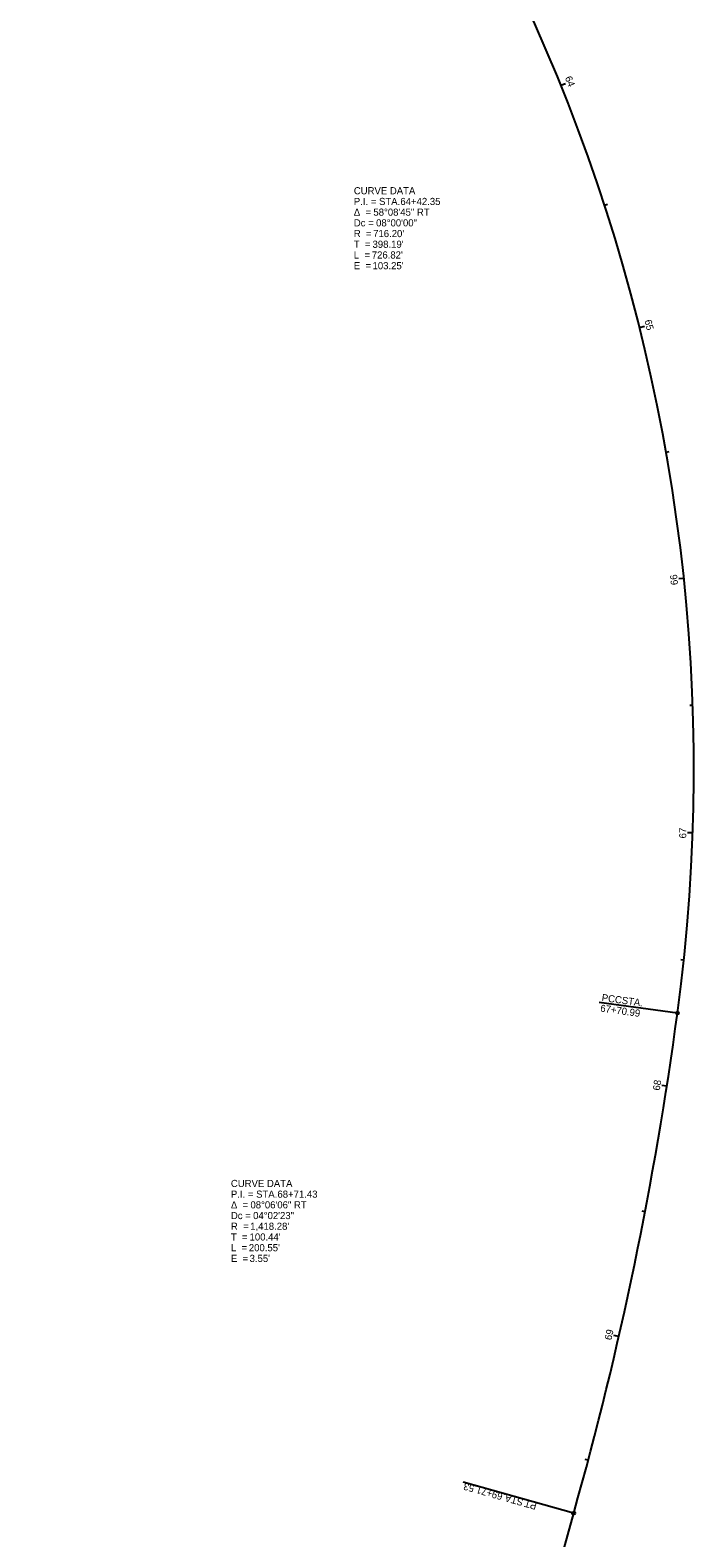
# Model space of a CAD drawing. Extents: x 2200534 to 2201952, y 633824 to 635634.
# Drawn here: x 2201692 to 2201952, y 634138 to 634730 of the extents above; entities that cross this region are included whole.
import ezdxf

# ---------------------------------------------------------------- set-up
doc = ezdxf.new("R2010")
doc.units = 0
for name, color, linetype in [('_CIVIL_CONSTRUCTION', 7, 'Continuous'), ('RW_X_CL', 7, 'Continuous'), ('RW_X_CL_100_Cardinal_Points', 7, 'Continuous'), ('SH_Data', 7, 'Continuous')]:
    doc.layers.add(name, color=color, linetype=linetype)

msp = doc.modelspace()

# ---------------------------------------------------------------- linework, layer by layer
at = {"layer": 'RW_X_CL'}
for p, q in [((2201946.02, 634344.04), (2201915.27, 634348.19)), ((2201905.29, 634147.85), (2201861.98, 634160.08))]:
    msp.add_line(p, q, dxfattribs=at)
for centre in [(2201946.02, 634344.04), (2201905.29, 634147.85)]:
    msp.add_circle(centre, 0.6, dxfattribs=at)
at = {"layer": 'RW_X_CL_100_Cardinal_Points'}
for p, q in [((2201900.27, 634708.03), (2201902.12, 634708.78)), ((2201917.37, 634661.06), (2201918.51, 634661.43)), ((2201931.15, 634613.01), (2201933.09, 634613.49)), ((2201941.55, 634564.11), (2201942.73, 634564.32)), ((2201948.51, 634514.61), (2201946.52, 634514.4)), ((2201952, 634464.74), (2201950.8, 634464.7)), ((2201952, 634414.75), (2201950, 634414.82)), ((2201948.51, 634364.88), (2201947.32, 634365.01)), ((2201941.85, 634315.33), (2201939.87, 634315.64)), ((2201933.29, 634266.07), (2201932.11, 634266.3)), ((2201923, 634217.15), (2201921.05, 634217.59)), ((2201910.99, 634168.61), (2201909.83, 634168.92))]:
    msp.add_line(p, q, dxfattribs=at)
at = {"layer": 'SH_Data'}
msp.add_line((2201905.29, 634147.85), (2201818.25, 633839.81), dxfattribs=at)
for centre, radius, start, end in [((2201236.24, 634439.71), 716.2, 352.32377, 50.4696), ((2201236.24, 634439.71), 716.2, 352.32377, 50.4696), ((2201236.24, 634439.71), 716.2, 352.32377, 50.4696), ((2200540.45, 634533.49), 1418.28, 344.2221, 352.32377), ((2200540.45, 634533.49), 1418.28, 344.2221, 352.32377)]:
    msp.add_arc(centre, radius, start, end, dxfattribs=at)

# ---------------------------------------------------------------- texts
at = {"layer": '_CIVIL_CONSTRUCTION'}
for s, p in [('CURVE DATA', (2201819.05, 634665.27)), ('P.I. = STA. ', (2201819.05, 634661.07)), ('64+42.35', (2201837.32, 634661.07)), ('Δ  = ', (2201819.05, 634656.87)), ('58°08\'45" RT', (2201826.73, 634656.87)), ('Dc = ', (2201819.05, 634652.67)), ('08°00\'00"', (2201827.79, 634652.67)), ('T  = ', (2201819.05, 634644.27)), ('R  = ', (2201819.05, 634648.47)), ("398.19'", (2201826.39, 634644.27)), ("716.20'", (2201826.63, 634648.47)), ('L  = ', (2201819.05, 634640.07)), ("726.82'", (2201826.09, 634640.07)), ('E  = ', (2201819.05, 634635.87)), ("103.25'", (2201826.39, 634635.87)), ('CURVE DATA', (2201770.83, 634275.83)), ('P.I. = STA. ', (2201770.83, 634271.63)), ('68+71.43', (2201789.09, 634271.63)), ('Δ  = ', (2201770.83, 634267.43)), ('08°06\'06" RT', (2201778.5, 634267.43)), ('Dc = ', (2201770.83, 634263.23)), ('R  = ', (2201770.83, 634259.03)), ("1,418.28'", (2201778.41, 634259.03)), ('04°02\'23"', (2201779.56, 634263.23)), ('T  = ', (2201770.83, 634254.83)), ("100.44'", (2201778.16, 634254.83)), ('L  = ', (2201770.83, 634250.63)), ('E  = ', (2201770.83, 634246.43)), ("200.55'", (2201777.87, 634250.63)), ("3.55'", (2201778.17, 634246.43))]:
    msp.add_text(s, height=2.8, dxfattribs=at).set_placement(p)
at = {"layer": 'RW_X_CL'}
for s, rotation, p in [('PCC', 352.32377, (2201916.16, 634348.81)), (' STA. ', 352.32377, (2201922.99, 634347.89)), ('67+70.99', 352.32377, (2201915.6, 634344.65)), ('69+71.53', 164.2221, (2201877.7, 634155.6)), (' STA. ', 164.2221, (2201886.8, 634153.03)), ('PT', 164.2221, (2201891.05, 634151.83))]:
    msp.add_text(s, height=2.8, rotation=rotation, dxfattribs=at).set_placement(p)
at = {"layer": 'RW_X_CL_100_Cardinal_Points'}
for s, rotation, p in [('64', 292.00281, (2201901.78, 634710.97)), ('65', 284.00281, (2201933.05, 634615.73)), ('66', 96.00281, (2201946.25, 634512.12)), ('67', 88.00281, (2201949.42, 634412.54)), ('68', 81.15174, (2201939.04, 634313.53)), ('69', 77.11192, (2201920.07, 634215.56))]:
    msp.add_text(s, height=2.8, rotation=rotation, dxfattribs=at).set_placement(p)

doc.saveas('drawing.dxf')
